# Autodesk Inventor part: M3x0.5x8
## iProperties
Company: 한국ATC센터
Created: 2009-02
Part Number: M3x0.5x8
Document SubType Name: Modeling
Designer: KYOUNG IL JANG
Density: 2.71 g/cm^3
Mass: 114.339 g
Surface Area: 117.889 cm^2
Volume: 42.1916 cm^3
Material: 알루미늄-6061
Vendor: CBT Solutions
Author: KYOUNG IL JANG
